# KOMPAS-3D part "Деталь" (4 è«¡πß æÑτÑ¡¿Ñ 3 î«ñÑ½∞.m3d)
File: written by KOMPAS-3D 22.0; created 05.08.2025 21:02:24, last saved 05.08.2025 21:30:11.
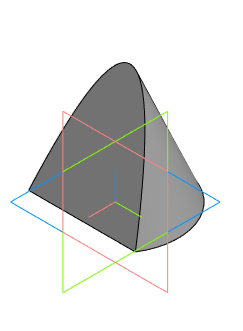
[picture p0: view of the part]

Document properties: Автор: user; Полное имя файла: G:\08 05 вторник\2025 НГ Лаб работы\Лаб 4 Сечение конуса\4 Модели\4 Конус Сечение 5 Модель.m3d

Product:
- Part/product: Деталь
    Масса: 0.348499

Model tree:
1. Эскиз:1
2. Элемент вращения:1
     Угол 1 = 360
3. Эскиз:2  (with: Элемент вращения:1)
4. Элемент выдавливания:1
     Расстояние 1 = 30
